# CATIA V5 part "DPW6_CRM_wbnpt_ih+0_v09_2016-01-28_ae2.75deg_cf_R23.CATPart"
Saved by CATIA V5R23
Part number: DPW6_CRM_wbnpt_ih+0_v09_2016-01-28_ae2
Bounding box of the stored display mesh (mm): x 2349.5 to 66711.883, y -0.003 to 29451.242, z -66.043 to 8715.764
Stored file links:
  C:\Users\mrg\work\AIAA_DPW\DPW6\DLR_meshes\all\2deg75\DPW6_CRM_wbnpt_ih+0_v09_2016-01-28_ae2.75deg_cf_R23.CATPart

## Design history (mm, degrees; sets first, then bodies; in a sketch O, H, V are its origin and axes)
MechanicalRefPlane1 "xy-plane"
MechanicalRefPlane2 "yz-plane"
MechanicalRefPlane3 "zx-plane"
Set1
  DatumSurface1 to DatumSurface3
Body1 (main body)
